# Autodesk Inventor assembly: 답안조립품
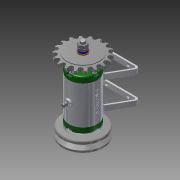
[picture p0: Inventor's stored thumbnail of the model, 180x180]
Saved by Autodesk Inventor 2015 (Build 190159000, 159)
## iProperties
Created: 2016-03
Part Number: 답안조립품
Document SubType Name: Assembly
Designer: Administrator
Author: Administrator
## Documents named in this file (16)
- C:\Users\Administrator\Desktop\답안조립품.iam
- C:\Users\Administrator\Desktop\본체.ipt
- C:\Users\Administrator\Desktop\460307V1013\베어링 15 x 32 x 9.ipt
- C:\Users\Administrator\Desktop\460307V1013\오일 실 15 25 7.ipt
- C:\Users\Administrator\Desktop\460307V1013\커버.ipt
- C:\Users\Administrator\Desktop\460307V1013\볼트 M4 x 12.ipt
- C:\Users\Administrator\Desktop\460307V1013\축.ipt
- C:\Users\Administrator\Desktop\460307V1013\V벨트풀리.ipt
- C:\Users\Administrator\Desktop\460307V1013\스프로킷.ipt
- C:\Users\Administrator\Desktop\460307V1013\키 3 x 3 x 12.ipt
- C:\Users\Administrator\Desktop\460307V1013\와셔 8x17.ipt
- C:\Users\Administrator\Desktop\460307V1013\스프링와셔 8.ipt
- C:\Users\Administrator\Desktop\460307V1013\너트 M 8.ipt
- C:\Users\Administrator\Desktop\460307V1013\볼트 M 6 x 8.ipt
- C:\Users\Administrator\Desktop\460307V1013\와셔 6x11.5.ipt
- C:\Users\Administrator\Desktop\460307V1013\니플 M 6 x 0.75.ipt
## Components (11 placed, 3 different names)
1. KS B 2023 6002 - 15 x 32 x 9:1
2. KS B 2023 6002 - 15 x 32 x 9:2
3. ISO 4762 M4 x 12:1 — 각도:7, 각도:8
4. ISO 4762 M4 x 12:2 — 각도:8
5. ISO 4762 M4 x 12:3 — 각도:5, 각도:6
6. ISO 4762 M4 x 12:4 — 각도:6, 각도:7
7. ISO 4762 M4 x 12:5 — 각도:3, 각도:4
8. ISO 4762 M4 x 12:6 — 각도:4
9. ISO 4762 M4 x 12:7 — 각도:1, 각도:2
10. ISO 4762 M4 x 12:8 — 각도:2, 각도:3
11. V벨트풀리:1 — 각도:9
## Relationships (9: Angle 9)
- 각도:1 [Angle]: ISO 4762 M4 x 12:7
- 각도:2 [Angle]: ISO 4762 M4 x 12:7 ↔ ISO 4762 M4 x 12:8
- 각도:3 [Angle]: ISO 4762 M4 x 12:5 ↔ ISO 4762 M4 x 12:8
- 각도:4 [Angle]: ISO 4762 M4 x 12:5 ↔ ISO 4762 M4 x 12:6
- 각도:5 [Angle]: ISO 4762 M4 x 12:3
- 각도:6 [Angle]: ISO 4762 M4 x 12:3 ↔ ISO 4762 M4 x 12:4
- 각도:7 [Angle]: ISO 4762 M4 x 12:1 ↔ ISO 4762 M4 x 12:4
- 각도:8 [Angle]: ISO 4762 M4 x 12:1 ↔ ISO 4762 M4 x 12:2
- 각도:9 [Angle]: V벨트풀리:1
